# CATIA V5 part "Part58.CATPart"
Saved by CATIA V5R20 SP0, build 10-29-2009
Part number: 9AE103036-3
Revision: ANY
Definition: UNKNOWN
Nomenclature: 9AE103036-3
Source: Unknown
Bounding box of the stored display mesh (mm): x -12.15 to 23.35, y -37 to 55, z -17.569 to 17.569
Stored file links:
  C:\Users\Utente\Desktop\IO LAVORO\3D X SITO CF\CUMSA\3D files AE\Part58.CATPart
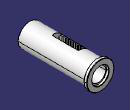
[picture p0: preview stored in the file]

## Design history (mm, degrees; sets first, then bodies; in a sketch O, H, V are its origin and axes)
Set1 "FacciaKO#NONE#11959"
  DatumSurface1 "Sup11959_1"
  DatumCurve1 "Crv11959_1"
Set2 "FacciaKO#NONE#4986"
  DatumSurface2 "Sup4986_1"
  DatumCurve2 "Crv4986_1"
Set3 "FacciaKO#NONE#5555"
  DatumSurface3 "Sup5555_1"
  DatumCurve3 "Crv5555_1"
Set4 "FacciaKO#NONE#15734"
  DatumSurface4 "Sup15734_1"
  DatumCurve4 "Crv15734_1"
Body1 "Cortar-Barrer1" (main body)
  Solid1: solid without history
